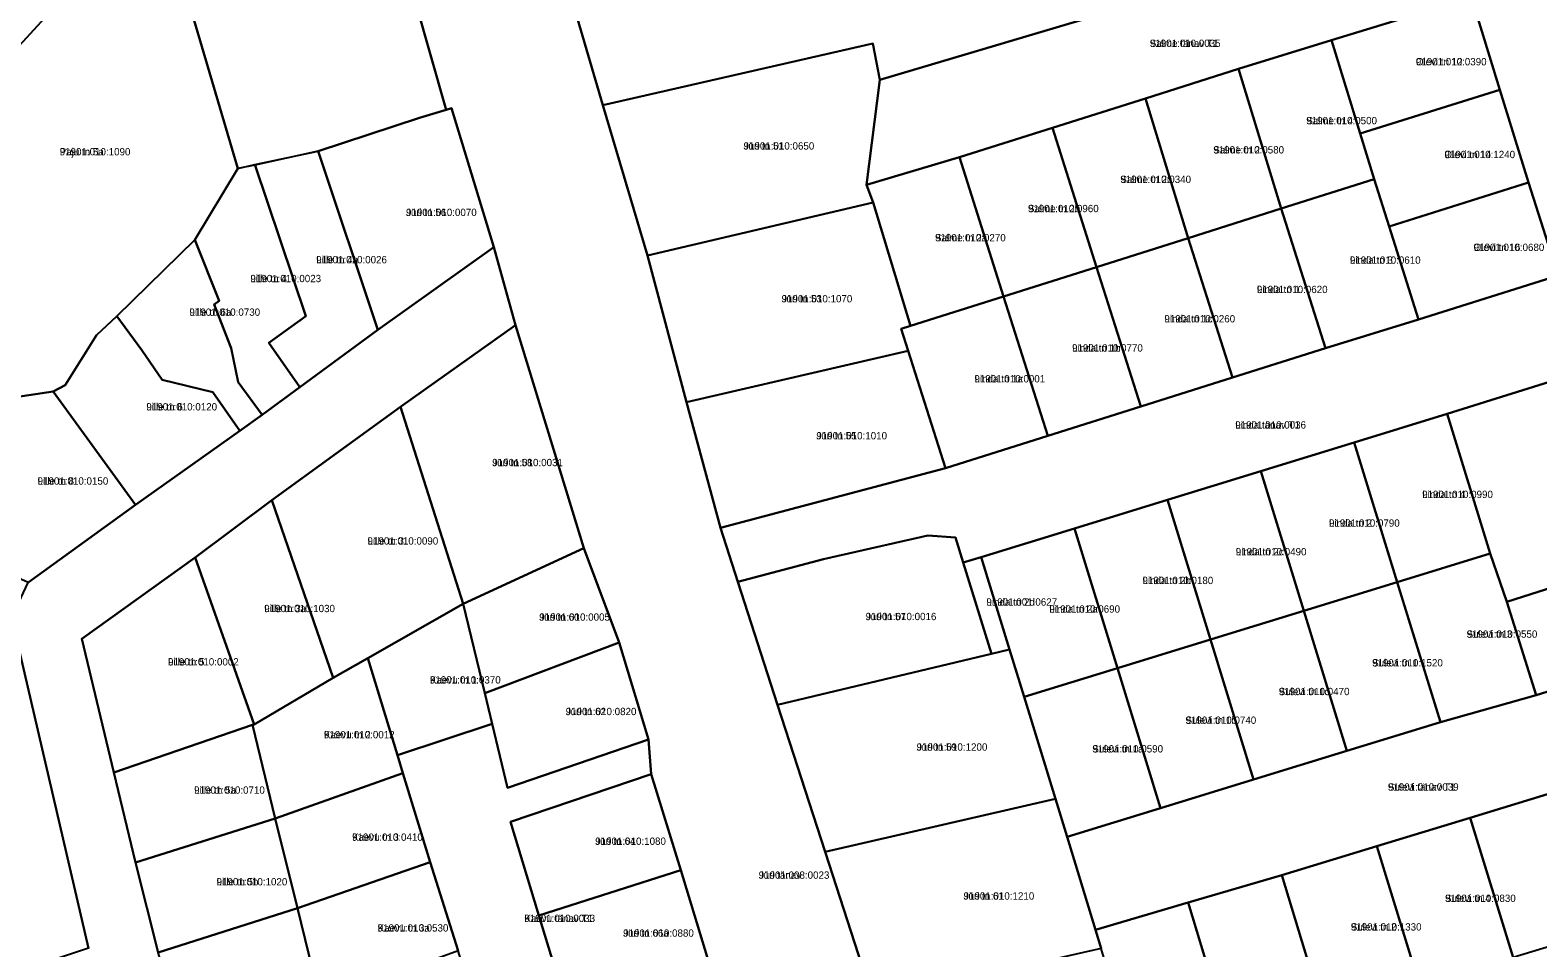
# Model space of a CAD drawing. Extents: x 675810 to 681273, y 6411190 to 6417565.
# Drawn here: x 678420.5 to 678729.6, y 6414897.2 to 6415085.5 of the extents above; entities that cross this region are included whole.
import ezdxf

# ---------------------------------------------------------------- set-up
doc = ezdxf.new("R2010")
doc.units = 0
for name, color, linetype in [('L_AADRESS', 7, 'Continuous'), ('PIIR', 7, 'Continuous'), ('TUNNUS', 7, 'Continuous')]:
    doc.layers.add(name, color=color, linetype=linetype)

msp = doc.modelspace()

# ---------------------------------------------------------------- linework, layer by layer
at = {"layer": 'PIIR'}
for points in [[(678559.96, 6414893.12), (678553.89, 6414913.15), (678547.84, 6414932.86), (678547.28, 6414939.98), (678541.29, 6414959.88), (678534.04, 6414979.2), (678520.02, 6415024.94), (678515.55, 6415040.95), (678506.86, 6415069.47), (678505.8, 6415069.15), (678490.24, 6415123.71), (678485.45, 6415140.4), (678483.26, 6415139.74), (678475.58, 6415166.43), (678471.76, 6415169.14), (678462.12, 6415184.59), (678461.97, 6415187.74), (678430.14, 6415214.96), (678394.49, 6415246.32)], [(678478.18, 6415236.44), (678505.53, 6415212.72), (678515.07, 6415188.65), (678514.96, 6415148.49), (678518.19, 6415137.48), (678528.56, 6415102.07), (678537.93, 6415070.11), (678547.05, 6415039.23), (678555.05, 6415009.15), (678562.02, 6414983.35), (678565.58, 6414972.33), (678573.75, 6414947.07), (678583.53, 6414916.89), (678593.38, 6414886.44)], [(678733.78, 6415035.16), (678727.76, 6415054.23), (678721.83, 6415073.27), (678716.04, 6415092.22), (678710.64, 6415110.33), (678704.61, 6415129.57), (678698.75, 6415148.62), (678692.65, 6415168.36), (678686.86, 6415187.48), (678679.92, 6415209.28), (678698.84, 6415212.11), (678721.36, 6415140.44), (678729.87, 6415113.29)], [(678432.46, 6414897.13), (678417.78, 6414960.39), (678415.33, 6414962.05), (678420.05, 6414972.18), (678442.05, 6414988.11), (678463.49, 6415003.25), (678468.06, 6415006.53), (678475.79, 6415012.25), (678491.76, 6415023.99), (678515.55, 6415040.95), (678520.02, 6415024.94), (678496.43, 6415008.17), (678470.05, 6414989.05), (678454.33, 6414977.28), (678431.1, 6414960.63), (678437.67, 6414933.19), (678442.1, 6414914.71), (678446.71, 6414896.28)]]:
    msp.add_lwpolyline(points, dxfattribs=at)
for points in [[(678449.54, 6415103.08), (678448.65, 6415111.86), (678490.24, 6415123.71), (678505.8, 6415069.15), (678500.3, 6415067.48), (678479.56, 6415060.67), (678466.56, 6415057.81), (678463.07, 6415057.11)], [(678626.94, 6415123.82), (678628.27, 6415117.9), (678635.23, 6415087.35), (678594.74, 6415075.31), (678593.3, 6415082.73), (678537.93, 6415070.11), (678528.56, 6415102.07)], [(678392.56, 6415017.82), (678372.11, 6415027.37), (678374.81, 6415033.31), (678388.99, 6415057.91), (678395.5, 6415064.65), (678403.78, 6415072.65), (678406.87, 6415069.96), (678423.48, 6415087.99), (678404.98, 6415106.41), (678408.56, 6415109.92), (678426.73, 6415090.88), (678449.54, 6415103.08), (678463.07, 6415057.11), (678454.26, 6415042.47), (678438.23, 6415026.81), (678434.07, 6415022.91), (678427.68, 6415012.64), (678425.23, 6415011.38), (678413.81, 6415009.65)], [(678594.74, 6415075.31), (678635.23, 6415087.35), (678662.35, 6415094.95), (678661.98, 6415096.21), (678681.83, 6415101.98), (678710.64, 6415110.33), (678716.04, 6415092.22), (678687.36, 6415083.46), (678668.25, 6415077.57), (678649.18, 6415071.49), (678630.1, 6415065.46), (678611.03, 6415059.43), (678591.98, 6415053.76)], [(678380.55, 6415080.49), (678404.98, 6415106.41), (678423.48, 6415087.99), (678406.87, 6415069.96), (678403.78, 6415072.65), (678395.5, 6415064.65)], [(678687.36, 6415083.46), (678716.04, 6415092.22), (678721.83, 6415073.27), (678693.21, 6415064.31)], [(678677.02, 6415048.88), (678668.25, 6415077.57), (678687.36, 6415083.46), (678693.21, 6415064.31), (678696.08, 6415054.92)], [(678593.3, 6415082.73), (678594.74, 6415075.31), (678591.98, 6415053.76), (678593.34, 6415050.11), (678547.05, 6415039.23), (678537.93, 6415070.11)], [(678657.96, 6415042.8), (678649.18, 6415071.49), (678668.25, 6415077.57), (678677.02, 6415048.88)], [(678630.1, 6415065.46), (678649.18, 6415071.49), (678657.96, 6415042.8), (678639.15, 6415036.85)], [(678727.76, 6415054.23), (678699.15, 6415045.19), (678696.08, 6415054.92), (678693.21, 6415064.31), (678721.83, 6415073.27)], [(678515.55, 6415040.95), (678491.76, 6415023.99), (678479.56, 6415060.67), (678500.3, 6415067.48), (678505.8, 6415069.15), (678506.86, 6415069.47)], [(678611.03, 6415059.43), (678630.1, 6415065.46), (678639.15, 6415036.85), (678620.08, 6415030.83)], [(678466.53, 6415057.89), (678479.56, 6415060.67), (678491.76, 6415023.99), (678475.79, 6415012.25), (678469.42, 6415021.34), (678477.03, 6415026.83)], [(678591.98, 6415053.76), (678611.03, 6415059.43), (678620.08, 6415030.83), (678601.01, 6415024.79), (678593.34, 6415050.11)], [(678463.07, 6415057.11), (678466.53, 6415057.89), (678477.03, 6415026.83), (678469.42, 6415021.34), (678475.79, 6415012.25), (678468.06, 6415006.53), (678463.16, 6415013.29), (678461.67, 6415020.23), (678458.19, 6415029.18), (678459.26, 6415029.94), (678454.26, 6415042.47)], [(678696.08, 6415054.92), (678699.15, 6415045.19), (678705.19, 6415026.12), (678686.1, 6415020.24), (678677.02, 6415048.88)], [(678699.15, 6415045.19), (678727.76, 6415054.23), (678733.78, 6415035.16), (678705.19, 6415026.12)], [(678555.05, 6415009.15), (678547.05, 6415039.23), (678593.34, 6415050.11), (678601.01, 6415024.79), (678599.11, 6415024.19), (678600.53, 6415019.71)], [(678677.02, 6415048.88), (678686.1, 6415020.24), (678667, 6415014.19), (678657.96, 6415042.8)], [(678639.15, 6415036.85), (678657.96, 6415042.8), (678667, 6415014.19), (678648.2, 6415008.25)], [(678463.16, 6415013.29), (678468.06, 6415006.53), (678463.49, 6415003.25), (678457.92, 6415011.22), (678447.53, 6415013.76), (678443.35, 6415019.81), (678438.23, 6415026.81), (678454.26, 6415042.47), (678459.26, 6415029.94), (678458.19, 6415029.18), (678461.67, 6415020.23)], [(678629.13, 6415002.22), (678620.08, 6415030.83), (678639.15, 6415036.85), (678648.2, 6415008.25)], [(678562.02, 6414983.35), (678608.15, 6414995.6), (678629.13, 6415002.22), (678648.2, 6415008.25), (678667, 6415014.19), (678686.1, 6415020.24), (678705.19, 6415026.12), (678733.78, 6415035.16), (678739.92, 6415015.81), (678711.08, 6415006.77), (678691.97, 6415000.89), (678672.85, 6414995.01), (678653.73, 6414989.12), (678634.61, 6414983.24), (678615.5, 6414977.36), (678611.82, 6414976.26), (678610.23, 6414981.4), (678604.57, 6414981.8), (678583.13, 6414976.97), (678565.58, 6414972.33)], [(678620.08, 6415030.83), (678629.13, 6415002.22), (678608.15, 6414995.6), (678600.53, 6415019.71), (678599.11, 6415024.19), (678601.01, 6415024.79)], [(678463.49, 6415003.25), (678442.05, 6414988.11), (678425.23, 6415011.38), (678427.68, 6415012.64), (678434.07, 6415022.91), (678438.23, 6415026.81), (678443.35, 6415019.81), (678447.53, 6415013.76), (678457.92, 6415011.22)], [(678520.02, 6415024.94), (678534.04, 6414979.2), (678509.28, 6414967.77), (678496.43, 6415008.17)], [(678608.15, 6414995.6), (678562.02, 6414983.35), (678555.05, 6415009.15), (678600.53, 6415019.71)], [(678743.51, 6414983), (678745.76, 6414975.36), (678723.29, 6414968.17), (678719.9, 6414978.09), (678711.08, 6415006.77), (678739.92, 6415015.81), (678749.26, 6414984.72)], [(678420.05, 6414972.18), (678401.96, 6414980.22), (678413.81, 6415009.65), (678425.23, 6415011.38), (678442.05, 6414988.11)], [(678482.64, 6414952.61), (678470.05, 6414989.05), (678496.43, 6415008.17), (678509.28, 6414967.77), (678489.72, 6414956.65)], [(678719.9, 6414978.09), (678700.79, 6414972.21), (678691.97, 6415000.89), (678711.08, 6415006.77)], [(678700.79, 6414972.21), (678681.67, 6414966.33), (678672.85, 6414995.01), (678691.97, 6415000.89)], [(678681.67, 6414966.33), (678662.55, 6414960.45), (678653.73, 6414989.12), (678672.85, 6414995.01)], [(678354.51, 6414990.92), (678415.33, 6414962.05), (678417.78, 6414960.39), (678432.46, 6414897.13), (678385.96, 6414881.65), (678382.75, 6414889.63), (678367.32, 6414929.45), (678364.9, 6414932.05), (678343.14, 6414955.25), (678343.17, 6414963.4), (678335.38, 6414971.24), (678338.95, 6414974.66), (678347.59, 6414983.69)], [(678470.05, 6414989.05), (678482.64, 6414952.61), (678466.41, 6414943.06), (678454.33, 6414977.28)], [(678634.61, 6414983.24), (678653.73, 6414989.12), (678662.55, 6414960.45), (678643.44, 6414954.57)], [(678610.23, 6414981.4), (678611.82, 6414976.26), (678617.62, 6414957.56), (678573.75, 6414947.07), (678565.58, 6414972.33), (678583.13, 6414976.97), (678604.57, 6414981.8)], [(678643.44, 6414954.57), (678624.32, 6414948.69), (678621.32, 6414958.43), (678615.5, 6414977.36), (678634.61, 6414983.24)], [(678534.04, 6414979.2), (678541.29, 6414959.88), (678513.73, 6414949.43), (678509.28, 6414967.77)], [(678723.29, 6414968.17), (678729.28, 6414949.08), (678709.66, 6414943.54), (678700.79, 6414972.21), (678719.9, 6414978.09)], [(678454.33, 6414977.28), (678466.41, 6414943.06), (678466.04, 6414942.94), (678437.67, 6414933.19), (678431.1, 6414960.63)], [(678615.5, 6414977.36), (678621.32, 6414958.43), (678617.62, 6414957.56), (678611.82, 6414976.26)], [(678723.29, 6414968.17), (678745.76, 6414975.36), (678751.51, 6414977.02), (678757.87, 6414958), (678729.28, 6414949.08)], [(678690.49, 6414937.66), (678681.67, 6414966.33), (678700.79, 6414972.21), (678709.66, 6414943.54)], [(678515.23, 6414943.19), (678495.79, 6414936.76), (678489.72, 6414956.65), (678509.28, 6414967.77), (678513.73, 6414949.43)], [(678671.37, 6414931.77), (678662.55, 6414960.45), (678681.67, 6414966.33), (678690.49, 6414937.66)], [(678518.39, 6414930.01), (678515.23, 6414943.19), (678513.73, 6414949.43), (678541.29, 6414959.88), (678547.28, 6414939.98)], [(678643.44, 6414954.57), (678662.55, 6414960.45), (678671.37, 6414931.77), (678652.26, 6414925.89)], [(678489.72, 6414956.65), (678495.79, 6414936.76), (678496.88, 6414933.02), (678470.71, 6414923.75), (678466.04, 6414942.94), (678466.41, 6414943.06), (678482.64, 6414952.61)], [(678621.32, 6414958.43), (678624.32, 6414948.69), (678630.76, 6414927.75), (678583.53, 6414916.89), (678573.75, 6414947.07), (678617.62, 6414957.56)], [(678633.14, 6414920.01), (678652.26, 6414925.89), (678671.37, 6414931.77), (678690.49, 6414937.66), (678709.66, 6414943.54), (678729.28, 6414949.08), (678757.87, 6414958), (678763.64, 6414938.53), (678734.94, 6414929.77), (678715.79, 6414923.89), (678696.65, 6414918.05), (678677.15, 6414912.15), (678657.96, 6414906.51), (678638.95, 6414900.92)], [(678633.14, 6414920.01), (678630.76, 6414927.75), (678624.32, 6414948.69), (678643.44, 6414954.57), (678652.26, 6414925.89)], [(678437.67, 6414933.19), (678466.04, 6414942.94), (678470.71, 6414923.75), (678442.1, 6414914.71)], [(678495.79, 6414936.76), (678515.23, 6414943.19), (678518.39, 6414930.01), (678547.28, 6414939.98), (678547.84, 6414932.86), (678518.97, 6414923.08), (678524.77, 6414903.82), (678528.02, 6414893.32), (678510.93, 6414888.02), (678508.26, 6414896.57), (678502.48, 6414914.78), (678496.88, 6414933.02)], [(678496.88, 6414933.02), (678502.48, 6414914.78), (678475.32, 6414905.32), (678470.71, 6414923.75)], [(678553.89, 6414913.15), (678524.77, 6414903.82), (678518.97, 6414923.08), (678547.84, 6414932.86)], [(678734.94, 6414929.77), (678740.77, 6414910.65), (678740.89, 6414910.26), (678743.69, 6414901.05), (678724.56, 6414895.21), (678715.79, 6414923.89)], [(678593.38, 6414886.44), (678583.53, 6414916.89), (678630.76, 6414927.75), (678633.14, 6414920.01), (678638.95, 6414900.92), (678640.11, 6414897.1)], [(678475.32, 6414905.32), (678446.71, 6414896.28), (678442.1, 6414914.71), (678470.71, 6414923.75)], [(678715.79, 6414923.89), (678721.63, 6414904.79), (678724.56, 6414895.21), (678705.42, 6414889.37), (678696.65, 6414918.05)], [(678696.65, 6414918.05), (678705.42, 6414889.37), (678685.83, 6414883.44), (678677.15, 6414912.15)], [(678508.26, 6414896.57), (678487.58, 6414889.09), (678479.95, 6414886.33), (678475.32, 6414905.32), (678502.48, 6414914.78)], [(678524.77, 6414903.82), (678553.89, 6414913.15), (678559.96, 6414893.12), (678530.75, 6414885.82), (678528.02, 6414893.32)], [(678666.64, 6414877.8), (678657.96, 6414906.51), (678677.15, 6414912.15), (678685.83, 6414883.44)], [(678452.2, 6414878.03), (678446.71, 6414896.28), (678475.32, 6414905.32), (678479.95, 6414886.33)], [(678647.45, 6414872.15), (678640.11, 6414897.1), (678638.95, 6414900.92), (678657.96, 6414906.51), (678666.64, 6414877.8)]]:
    msp.add_lwpolyline(points, close=True, dxfattribs=at)

# ---------------------------------------------------------------- texts
at = {"layer": 'L_AADRESS'}
for s, p in [('Salme tänav T1', (678650.08, 6415082.04)), ('Olevi tn 12', (678704.63, 6415078.26)), ('Salme tn 4', (678682.16, 6415066.18)), ('Paju tn 5a', (678426.54, 6415059.79)), ('Jüri tn 51', (678566.77, 6415060.98)), ('Salme tn 2', (678663.1, 6415060.18)), ('Olevi tn 14', (678710.48, 6415059.23)), ('Salme tn 2c', (678644.03, 6415054.13)), ('Salme tn 2b', (678625.09, 6415048.14)), ('Jüri tn 56', (678497.55, 6415047.35)), ('Salme tn 2a', (678606.03, 6415042.16)), ('Olevi tn 16', (678716.47, 6415040.18)), ('Lille tn 4a', (678479.14, 6415037.65)), ('Linda tn 3', (678691.11, 6415037.56)), ('Lille tn 4', (678465.64, 6415033.78)), ('Jüri tn 53', (678574.57, 6415029.63)), ('Linda tn 1', (678672.03, 6415031.54)), ('Lille tn 6a', (678453.14, 6415026.88)), ('Linda tn 1c', (678653.07, 6415025.52)), ('Linda tn 1b', (678634.14, 6415019.54)), ('Linda tn 1a', (678614.12, 6415013.21)), ('Lille tn 6', (678444.31, 6415007.46)), ('Jüri tn 55', (678581.69, 6415001.53)), ('Linda tänav T1', (678667.6, 6415003.74)), ('Jüri tn 58', (678515.23, 6414996.03)), ('Lille tn 8', (678422, 6414992.24)), ('Linda tn 4', (678705.93, 6414989.49)), ('Linda tn 2', (678686.82, 6414983.61)), ('Lille tn 3', (678489.66, 6414979.94)), ('Linda tn 2c', (678667.7, 6414977.73)), ('Linda tn 2b', (678648.58, 6414971.84)), ('Linda tn 2d', (678616.57, 6414967.41)), ('Lille tn 3a', (678468.48, 6414966.08)), ('Jüri tn 60', (678524.87, 6414964.32)), ('Jüri tn 57', (678591.81, 6414964.44)), ('Linda tn 2a', (678629.47, 6414965.97)), ('Sulevi tn 3', (678715.04, 6414960.83)), ('Lille tn 5', (678448.75, 6414955.14)), ('Sulevi tn 1', (678695.66, 6414954.94)), ('Kaevu tn 1', (678502.47, 6414951.44)), ('Sulevi tn 1c', (678676.52, 6414949.05)), ('Jüri tn 62', (678530.3, 6414944.95)), ('Sulevi tn 1b', (678657.4, 6414943.17)), ('Kaevu tn 2', (678480.72, 6414940.2)), ('Jüri tn 59', (678602.26, 6414937.66)), ('Sulevi tn 1a', (678638.29, 6414937.29)), ('Lille tn 5a', (678454.1, 6414928.83)), ('Sulevi tänav T1', (678698.9, 6414929.46)), ('Kaevu tn 3', (678486.49, 6414919.17)), ('Jüri tn 64', (678536.35, 6414918.34)), ('Jüri tänav', (678569.87, 6414911.38)), ('Lille tn 5b', (678458.71, 6414910.02)), ('Jüri tn 61', (678611.88, 6414907.1)), ('Sulevi tn 4', (678710.61, 6414906.63)), ('Kaevu tänav T1', (678521.82, 6414902.51)), ('Kaevu tn 3a', (678491.74, 6414900.55)), ('Jüri tn 66a', (678542.07, 6414899.49)), ('Sulevi tn 2', (678691.29, 6414900.76))]:
    msp.add_text(s, height=1.5, dxfattribs=at).set_placement(p)
at = {"layer": 'TUNNUS'}
for s, p in [('91901:010:0035', (678650.08, 6415082.04)), ('91901:010:0390', (678704.63, 6415078.26)), ('91901:010:0500', (678682.16, 6415066.18)), ('91901:010:1090', (678426.54, 6415059.79)), ('91901:010:0650', (678566.77, 6415060.98)), ('91901:010:0580', (678663.1, 6415060.18)), ('91901:010:1240', (678710.48, 6415059.23)), ('91901:010:0340', (678644.03, 6415054.13)), ('91901:010:0960', (678625.09, 6415048.14)), ('91901:010:0070', (678497.55, 6415047.35)), ('91901:010:0270', (678606.03, 6415042.16)), ('91901:010:0680', (678716.47, 6415040.18)), ('91901:010:0026', (678479.14, 6415037.65)), ('91901:010:0610', (678691.11, 6415037.56)), ('91901:010:0023', (678465.64, 6415033.78)), ('91901:010:1070', (678574.57, 6415029.63)), ('91901:010:0620', (678672.03, 6415031.54)), ('91901:010:0730', (678453.14, 6415026.88)), ('91901:010:0260', (678653.07, 6415025.52)), ('91901:010:0770', (678634.14, 6415019.54)), ('91901:010:0001', (678614.12, 6415013.21)), ('91901:010:0120', (678444.31, 6415007.46)), ('91901:010:1010', (678581.69, 6415001.53)), ('91901:010:0036', (678667.6, 6415003.74)), ('91901:010:0031', (678515.23, 6414996.03)), ('91901:010:0150', (678422, 6414992.24)), ('91901:010:0990', (678705.93, 6414989.49)), ('91901:010:0790', (678686.82, 6414983.61)), ('91901:010:0090', (678489.66, 6414979.94)), ('91901:010:0490', (678667.7, 6414977.73)), ('91901:010:0180', (678648.58, 6414971.84)), ('91901:001:0627', (678616.57, 6414967.41)), ('91901:010:1030', (678468.48, 6414966.08)), ('91901:010:0005', (678524.87, 6414964.32)), ('91901:010:0016', (678591.81, 6414964.44)), ('91901:010:0690', (678629.47, 6414965.97)), ('91901:010:0550', (678715.04, 6414960.83)), ('91901:010:0002', (678448.75, 6414955.14)), ('91901:010:1520', (678695.66, 6414954.94)), ('91901:010:0370', (678502.47, 6414951.44)), ('91901:010:0470', (678676.52, 6414949.05)), ('91901:010:0820', (678530.3, 6414944.95)), ('91901:010:0740', (678657.4, 6414943.17)), ('91901:010:0012', (678480.72, 6414940.2)), ('91901:010:1200', (678602.26, 6414937.66)), ('91901:010:0590', (678638.29, 6414937.29)), ('91901:010:0710', (678454.1, 6414928.83)), ('91901:010:0039', (678698.9, 6414929.46)), ('91901:010:0410', (678486.49, 6414919.17)), ('91901:010:1080', (678536.35, 6414918.34)), ('91901:010:1020', (678458.71, 6414910.02)), ('91901:008:0023', (678569.87, 6414911.38)), ('91901:010:1210', (678611.88, 6414907.1)), ('91901:010:0830', (678710.61, 6414906.63)), ('91901:010:0033', (678521.82, 6414902.51)), ('91901:010:0530', (678491.74, 6414900.55)), ('91901:010:0880', (678542.07, 6414899.49)), ('91901:010:1330', (678691.29, 6414900.76))]:
    msp.add_text(s, height=1.5, dxfattribs=at).set_placement(p)

doc.saveas('drawing.dxf')
